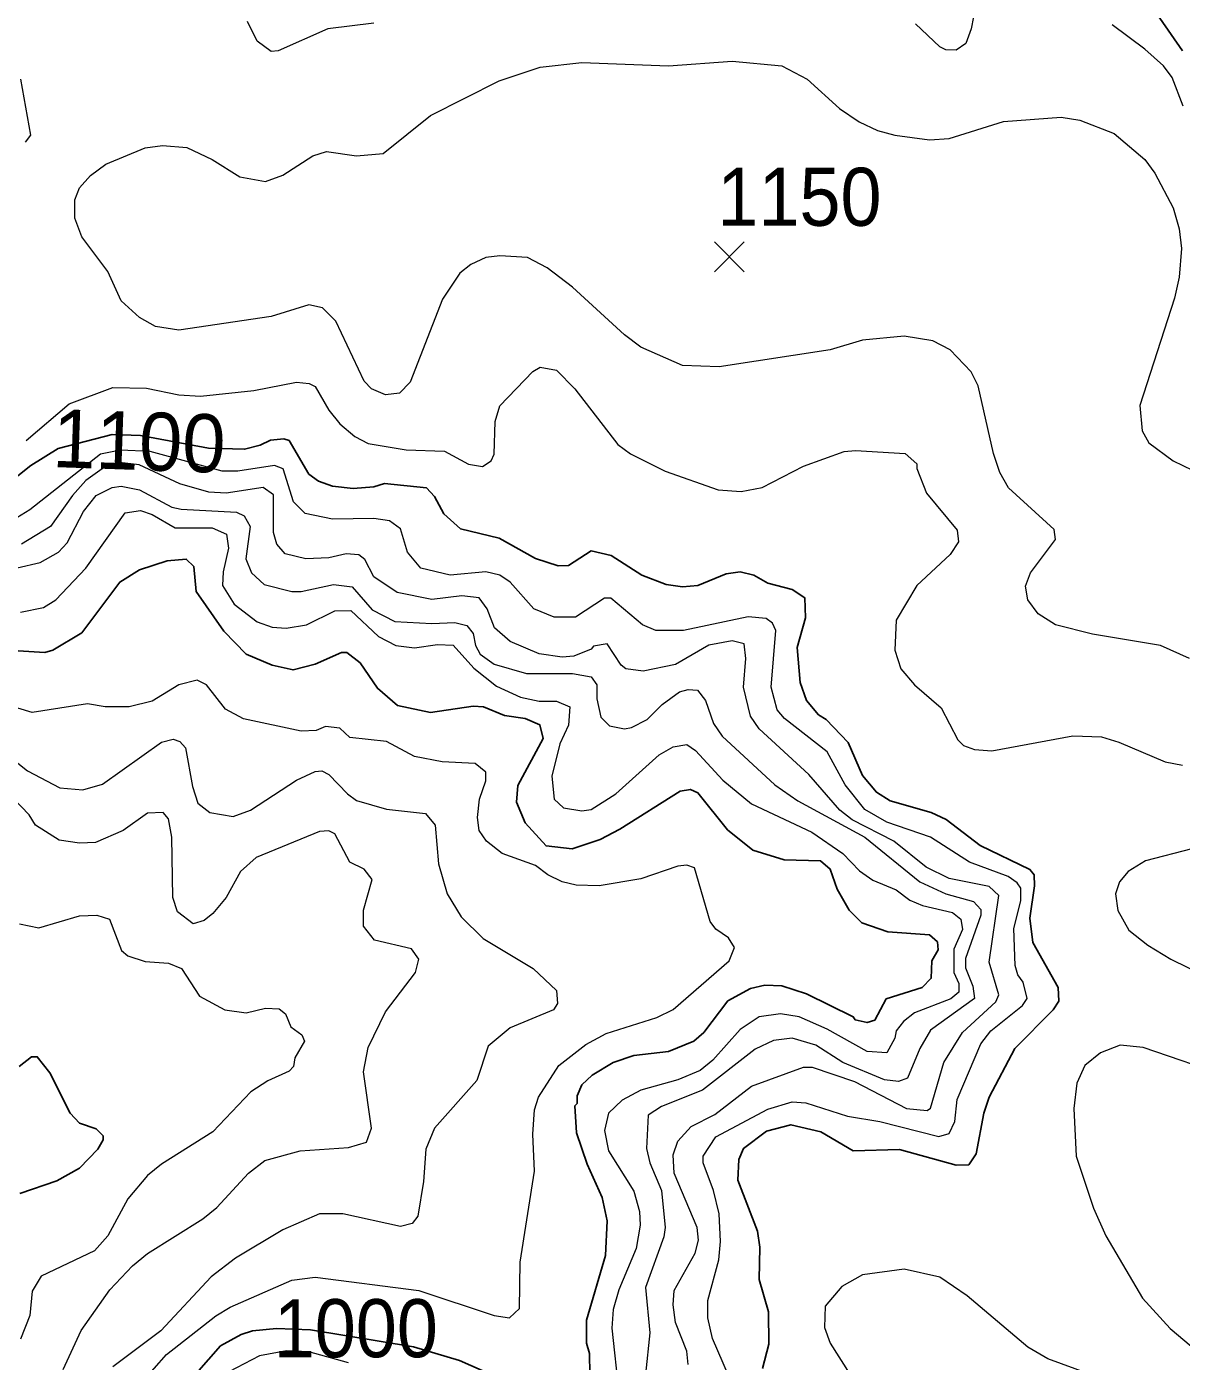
# Model space of a CAD drawing. Extents: x 265 to 291.4, y 7731.5 to 7759.6.
# Drawn here: x 268.417 to 270.007, y 7737.823 to 7739.662 of the extents above; entities that cross this region are included whole.
import ezdxf
from ezdxf.enums import TextEntityAlignment as Align

# ---------------------------------------------------------------- set-up
doc = ezdxf.new("R2010")
doc.units = 0
doc.header["$LTSCALE"] = 0.032
for name, color, linetype, lineweight in [('1', 7, 'Continuous', 25), ('2', 7, 'Continuous', 13), ('21', 7, 'Continuous', 25), ('61', 7, 'Continuous', 13)]:
    doc.layers.add(name, color=color, linetype=linetype, lineweight=lineweight)

msp = doc.modelspace()

# ---------------------------------------------------------------- linework, layer by layer
at = {"layer": '1'}
for points in [[(269.8961, 7739.759), (269.9207, 7739.7312), (269.9391, 7739.7185), (269.9621, 7739.6962), (270.009, 7739.6286)], [(269.1181, 7738.9293), (269.068, 7738.9572), (269.0147, 7738.9699), (268.9916, 7738.9906), (268.9789, 7739.0145), (268.9678, 7739.0264), (268.9097, 7739.0327), (268.8954, 7739.028), (268.8667, 7739.0256), (268.8381, 7739.0288), (268.819, 7739.0359), (268.8055, 7739.0455), (268.7784, 7739.0916), (268.7713, 7739.094), (268.753, 7739.0924), (268.7387, 7739.0852), (268.7172, 7739.0797), (268.6676, 7739.0813), (268.5739, 7739.0986), (268.5348, 7739.0999), (268.4604, 7739.0806), (268.4229, 7739.0574), (268.3497, 7738.9993)], [(269.2979, 7738.8935), (269.2645, 7738.9063), (269.2223, 7738.9333), (269.1945, 7738.9397), (269.1635, 7738.9198), (269.1491, 7738.919), (269.1181, 7738.9293)], [(268.4054, 7738.8021), (268.4419, 7738.7997), (268.4531, 7738.8028), (268.4929, 7738.8267), (268.5453, 7738.8967), (268.5724, 7738.9134), (268.6106, 7738.9262), (268.6368, 7738.9285), (268.6472, 7738.9182), (268.6504, 7738.884), (268.6885, 7738.8291), (268.7196, 7738.7973), (268.7554, 7738.7822), (268.784, 7738.7758), (268.8142, 7738.7838), (268.8508, 7738.7997), (268.858, 7738.7997), (268.8763, 7738.7853), (268.9001, 7738.7504), (268.928, 7738.7265), (268.9733, 7738.7169), (269.0322, 7738.7257), (269.0465, 7738.7249), (269.0752, 7738.713), (269.1038, 7738.709), (269.1237, 7738.7002), (269.1284, 7738.6812), (269.0934, 7738.6167), (269.0918, 7738.5936), (269.1038, 7738.565), (269.1324, 7738.5332), (269.1682, 7738.5292), (269.2072, 7738.5419), (269.2343, 7738.5562), (269.317, 7738.6087), (269.3313, 7738.6111), (269.3416, 7738.6064), (269.3822, 7738.5555), (269.4172, 7738.5276), (269.4602, 7738.5141), (269.5103, 7738.5125), (269.5238, 7738.5014), (269.5333, 7738.4735), (269.55, 7738.4449), (269.5675, 7738.4274), (269.6034, 7738.4147), (269.6606, 7738.4107), (269.6718, 7738.4011), (269.6726, 7738.39), (269.6638, 7738.3749), (269.663, 7738.351), (269.6503, 7738.3383), (269.601, 7738.3224), (269.5851, 7738.293), (269.5747, 7738.2898), (269.558, 7738.2937), (269.5556, 7738.2977), (269.4912, 7738.3295), (269.457, 7738.3407), (269.4339, 7738.3415)], [(269.4307, 7737.8133), (269.4395, 7737.8467), (269.4387, 7737.8912), (269.426, 7737.9358), (269.4268, 7737.9803), (269.4236, 7738.0026), (269.3965, 7738.0726), (269.3981, 7738.1013), (269.4045, 7738.1164), (269.4363, 7738.1402), (269.4697, 7738.149), (269.5111, 7738.1394), (269.5556, 7738.1132), (269.6193, 7738.1148), (269.6972, 7738.0933), (269.7147, 7738.0941), (269.7251, 7738.1092), (269.7354, 7738.1649), (269.7426, 7738.1872), (269.7783, 7738.254), (269.8309, 7738.3073), (269.8388, 7738.3192), (269.838, 7738.3383), (269.803, 7738.4004), (269.799, 7738.4338), (269.8054, 7738.4783), (269.8046, 7738.4934), (269.799, 7738.5006), (269.7306, 7738.534), (269.6837, 7738.5698), (269.663, 7738.5793), (269.6065, 7738.5952), (269.5874, 7738.6072), (269.5683, 7738.6302), (269.5484, 7738.6756), (269.5182, 7738.7074), (269.5079, 7738.7138), (269.4912, 7738.7337), (269.4824, 7738.7583), (269.4785, 7738.8068), (269.4896, 7738.8474), (269.4888, 7738.8752), (269.4713, 7738.8864), (269.4379, 7738.8951), (269.4188, 7738.9063), (269.3997, 7738.911), (269.3806, 7738.9079), (269.3416, 7738.8919), (269.3202, 7738.8904), (269.2979, 7738.8935)], [(269.4339, 7738.3415), (269.414, 7738.3367), (269.383, 7738.32), (269.3496, 7738.2763), (269.3361, 7738.2643), (269.3011, 7738.25), (269.2534, 7738.2444)], [(268.4077, 7738.0543), (268.4587, 7738.0718), (268.4897, 7738.0893), (268.5151, 7738.1156), (268.5223, 7738.1283), (268.5223, 7738.1339), (268.5128, 7738.1434), (268.4897, 7738.1514), (268.4769, 7738.1649), (268.4491, 7738.2206), (268.4316, 7738.2428), (268.4237, 7738.2428), (268.4069, 7738.2293)], [(269.2534, 7738.2444), (269.2247, 7738.2349), (269.1961, 7738.2174), (269.1817, 7738.2039), (269.1754, 7738.1888), (269.1754, 7738.1784), (269.1722, 7738.1752), (269.1746, 7738.1378), (269.1889, 7738.0949), (269.2096, 7738.0488), (269.2167, 7738.0169), (269.2144, 7737.9692), (269.1881, 7737.8801), (269.1881, 7737.8483), (269.1921, 7737.834), (269.1929, 7737.8053)], [(269.0799, 7737.795), (269.0131, 7737.8244), (268.9499, 7737.8433), (268.8078, 7737.8666), (268.7613, 7737.8685), (268.7283, 7737.865), (268.7124, 7737.8602), (268.6838, 7737.8443), (268.6376, 7737.7918)]]:
    msp.add_lwpolyline(points, dxfattribs=at)
at = {"layer": '2'}
for points in [[(269.7243, 7739.6922), (269.7179, 7739.6588), (269.7107, 7739.6389), (269.6972, 7739.6294), (269.6829, 7739.6302), (269.675, 7739.6341), (269.6415, 7739.666)], [(268.8954, 7739.6668), (268.8317, 7739.6588), (268.7633, 7739.6286), (268.7538, 7739.6278), (268.7347, 7739.6421), (268.7212, 7739.6692)], [(270.0098, 7739.5522), (269.9947, 7739.592), (269.9828, 7739.6079), (269.9574, 7739.631), (269.912, 7739.6644)], [(268.8302, 7739.4902), (268.8715, 7739.4838), (268.9081, 7739.487), (268.9733, 7739.5395), (269.068, 7739.5872), (269.1245, 7739.6063), (269.1818, 7739.6127)], [(269.1818, 7739.6127), (269.3011, 7739.6079), (269.3886, 7739.6143), (269.457, 7739.6079), (269.492, 7739.5896), (269.5365, 7739.549), (269.5636, 7739.5307), (269.589, 7739.5188), (269.6129, 7739.5124), (269.6606, 7739.5061), (269.6877, 7739.5077), (269.7625, 7739.5315), (269.842, 7739.5371), (269.8675, 7739.5331), (269.9152, 7739.5148), (269.9573, 7739.479), (269.9709, 7739.4599), (269.9963, 7739.4122), (270.0043, 7739.3836), (270.0075, 7739.3565), (270.0043, 7739.3168), (269.9979, 7739.2881), (269.9502, 7739.1402), (269.9534, 7739.1052), (269.9629, 7739.0884), (269.9963, 7739.0638), (270.0361, 7739.0447)], [(268.4085, 7739.5896), (268.4221, 7739.5124), (268.4149, 7739.5029)], [(270.0186, 7738.7917), (269.9788, 7738.8092), (269.885, 7738.8251), (269.8341, 7738.8379), (269.8102, 7738.853), (269.7959, 7738.8721), (269.7927, 7738.8912), (269.7998, 7738.9095), (269.834, 7738.9556), (269.8324, 7738.9691), (269.7696, 7739.0264), (269.7577, 7739.0479), (269.7489, 7739.0741), (269.7275, 7739.1672), (269.7179, 7739.1863), (269.6893, 7739.2165), (269.6654, 7739.2292), (269.6256, 7739.2356), (269.5684, 7739.23), (269.5238, 7739.2165), (269.3711, 7739.1935), (269.3202, 7739.195), (269.2629, 7739.2205), (269.2406, 7739.2372), (269.169, 7739.3032), (269.134, 7739.3295), (269.107, 7739.3438), (269.0688, 7739.3462), (269.0497, 7739.3438), (269.029, 7739.3342), (269.0139, 7739.3223), (268.99, 7739.2865), (268.9455, 7739.172), (268.9304, 7739.1569), (268.9113, 7739.1545), (268.8922, 7739.1632), (268.8818, 7739.1736), (268.8429, 7739.2563), (268.8246, 7739.2746), (268.8055, 7739.2786), (268.7538, 7739.2627), (268.6265, 7739.2436), (268.5947, 7739.2491), (268.5724, 7739.2611), (268.547, 7739.2841), (268.5287, 7739.3247), (268.4929, 7739.3724), (268.4833, 7739.3979), (268.4833, 7739.4234), (268.4897, 7739.44), (268.5048, 7739.4568), (268.5263, 7739.4727), (268.5804, 7739.4949), (268.6042, 7739.4981), (268.6376, 7739.4957), (268.6727, 7739.479), (268.7108, 7739.4552), (268.7458, 7739.4488), (268.7697, 7739.4575), (268.8111, 7739.4838), (268.8302, 7739.4902)], [(268.4165, 7739.0916), (268.4754, 7739.1425), (268.5358, 7739.1648), (268.582, 7739.164), (268.6265, 7739.1545), (268.6567, 7739.1529), (268.7299, 7739.1608), (268.7888, 7739.172), (268.8063, 7739.1704), (268.8142, 7739.1664), (268.8333, 7739.1338), (268.8484, 7739.1147), (268.8691, 7739.0972), (268.8874, 7739.0876), (268.9399, 7739.0789), (268.9924, 7739.0773), (269.0258, 7739.059), (269.0449, 7739.0558), (269.057, 7739.0637), (269.061, 7739.073), (269.0624, 7739.1179), (269.0688, 7739.1394), (269.1141, 7739.1871), (269.1245, 7739.1927), (269.1467, 7739.1887), (269.1722, 7739.1632), (269.2311, 7739.0861), (269.2486, 7739.0733), (269.2963, 7739.0495), (269.3695, 7739.024), (269.4013, 7739.0216), (269.43, 7739.0272), (269.4872, 7739.0566), (269.5429, 7739.0765), (269.5588, 7739.0781), (269.6272, 7739.0741), (269.6431, 7739.0598), (269.6431, 7739.0534), (269.6567, 7739.0192), (269.6988, 7738.9683), (269.7004, 7738.9524)], [(269.6956, 7738.1538), (269.6988, 7738.184), (269.7314, 7738.2604), (269.745, 7738.2786), (269.7887, 7738.3136), (269.7951, 7738.3232), (269.7895, 7738.3455), (269.7823, 7738.3558), (269.7784, 7738.3685), (269.7768, 7738.4195), (269.7863, 7738.4576), (269.7863, 7738.4751), (269.7815, 7738.4823), (269.7688, 7738.491), (269.7155, 7738.5109), (269.6622, 7738.5451), (269.6018, 7738.5658), (269.5715, 7738.5833), (269.5445, 7738.6175), (269.5198, 7738.6629), (269.461, 7738.709), (269.4506, 7738.7209), (269.4427, 7738.752), (269.449, 7738.8299), (269.4443, 7738.8403), (269.4355, 7738.8466), (269.4109, 7738.849), (269.3218, 7738.8299), (269.2836, 7738.8299), (269.2653, 7738.8379), (269.2215, 7738.8745), (269.2128, 7738.8745), (269.173, 7738.8482), (269.1436, 7738.8482), (269.1157, 7738.8601), (269.0831, 7738.8967), (269.0688, 7738.9063), (269.0497, 7738.911), (269.0004, 7738.9063), (268.9598, 7738.9158), (268.9415, 7738.9381), (268.932, 7738.9699), (268.9169, 7738.9811), (268.8954, 7738.9842), (268.8381, 7738.9834), (268.8007, 7738.9914), (268.7848, 7739.0073), (268.7705, 7739.0527), (268.7586, 7739.0574), (268.7077, 7739.0495), (268.6862, 7739.0495), (268.587, 7739.0767), (268.5464, 7739.0787), (268.5186, 7739.0728), (268.4213, 7738.9962), (268.3974, 7738.9818)], [(269.3281, 7737.8189), (269.3265, 7737.8372), (269.3106, 7737.8769), (269.3074, 7737.9008), (269.309, 7737.9207), (269.3377, 7737.9724), (269.3424, 7737.9899), (269.3408, 7738.0074), (269.309, 7738.0822), (269.3074, 7738.1076), (269.3138, 7738.1267), (269.3321, 7738.1466), (269.3647, 7738.1633), (269.4156, 7738.2023), (269.4872, 7738.2285), (269.4991, 7738.2285), (269.5572, 7738.2086), (269.6288, 7738.1713), (269.6575, 7738.1689), (269.6622, 7738.172), (269.6805, 7738.2349), (269.706, 7738.2763), (269.7521, 7738.3184), (269.7561, 7738.3279), (269.7426, 7738.3733), (269.7561, 7738.4648), (269.7426, 7738.4775), (269.6877, 7738.4886), (269.6559, 7738.5038), (269.6113, 7738.5396), (269.554, 7738.569), (269.5373, 7738.5825), (269.4944, 7738.6318), (269.426, 7738.6947), (269.414, 7738.7122), (269.4045, 7738.752), (269.4077, 7738.7917), (269.4053, 7738.8116), (269.3886, 7738.8156), (269.3568, 7738.81), (269.3106, 7738.783), (269.2661, 7738.7742), (269.2422, 7738.7774), (269.2358, 7738.7822), (269.2168, 7738.8116), (269.1977, 7738.8084), (269.1945, 7738.8044), (269.1706, 7738.7949), (269.1547, 7738.7933), (269.1229, 7738.7981), (269.0831, 7738.8148), (269.0616, 7738.8339), (269.0513, 7738.8601), (269.0402, 7738.8752), (269.0163, 7738.8776), (268.9749, 7738.8729), (268.9272, 7738.8824), (268.8954, 7738.9039), (268.8827, 7738.9278), (268.8747, 7738.9341), (268.8572, 7738.9357), (268.8333, 7738.9301), (268.8015, 7738.9286), (268.7729, 7738.9357), (268.7617, 7738.9492), (268.757, 7738.9652), (268.757, 7739.0169), (268.7427, 7739.0272), (268.6917, 7739.0192), (268.6679, 7739.0208), (268.6281, 7739.032), (268.5719, 7739.0584), (268.5447, 7739.0617), (268.5242, 7739.055), (268.4984, 7739.0367), (268.4801, 7739.0161), (268.4499, 7738.9731), (268.4101, 7738.9492)], [(268.3401, 7738.9015), (268.4356, 7738.9238), (268.4611, 7738.9381), (268.473, 7738.9508), (268.4952, 7738.9938), (268.5127, 7739.0161), (268.535, 7739.0272), (268.547, 7739.0288), (268.5724, 7739.024), (268.617, 7739.0001), (268.6297, 7738.997), (268.7061, 7738.993), (268.7164, 7738.9882), (268.7251, 7738.9731), (268.7188, 7738.9286), (268.7267, 7738.9095), (268.7442, 7738.8936), (268.7824, 7738.884), (268.7952, 7738.884), (268.8397, 7738.8936), (268.8652, 7738.8904), (268.893, 7738.8586), (268.924, 7738.8426), (268.9749, 7738.8395), (269.0068, 7738.841), (269.0235, 7738.8371), (269.0322, 7738.8259), (269.0354, 7738.8092), (269.0417, 7738.7973), (269.0608, 7738.7838), (269.1054, 7738.771), (269.169, 7738.771), (269.1945, 7738.7663), (269.2024, 7738.7551), (269.2024, 7738.7361), (269.208, 7738.7106), (269.2199, 7738.6987), (269.2406, 7738.6947), (269.2502, 7738.6963), (269.2716, 7738.7074), (269.2923, 7738.7281), (269.3162, 7738.7456), (269.3281, 7738.7488), (269.3409, 7738.748), (269.352, 7738.7337), (269.3631, 7738.7018), (269.375, 7738.6843), (269.4475, 7738.6175), (269.4793, 7738.5952), (269.5715, 7738.5451), (269.6471, 7738.4839), (269.6829, 7738.4672), (269.7211, 7738.4568), (269.7314, 7738.4457), (269.7314, 7738.4377), (269.71, 7738.3781), (269.71, 7738.3654), (269.7203, 7738.3399), (269.7227, 7738.3232), (269.6622, 7738.2794), (269.6471, 7738.254), (269.6304, 7738.2134), (269.6177, 7738.2086), (269.5986, 7738.211), (269.5413, 7738.2349), (269.5039, 7738.2588), (269.4713, 7738.2683), (269.4459, 7738.2651), (269.4204, 7738.2532), (269.348, 7738.1967), (269.2915, 7738.1744), (269.2732, 7738.1625), (269.2708, 7738.1164), (269.2756, 7738.0965), (269.2915, 7738.0583), (269.2963, 7738.0074), (269.2947, 7737.9947), (269.2693, 7737.9247), (269.2756, 7737.8626), (269.2693, 7737.8053)], [(268.4085, 7738.8554), (268.4404, 7738.8617), (268.4571, 7738.8721), (268.4984, 7738.9158), (268.5525, 7738.9922), (268.574, 7738.9954), (268.5899, 7738.9898), (268.6217, 7738.9715), (268.6727, 7738.9715), (268.6925, 7738.9628), (268.6949, 7738.9437), (268.6878, 7738.9111), (268.687, 7738.892), (268.7029, 7738.8665), (268.7347, 7738.8418), (268.7554, 7738.8347), (268.7745, 7738.8331), (268.8023, 7738.8379), (268.8413, 7738.857), (268.8636, 7738.8578), (268.9017, 7738.822), (268.9256, 7738.8092), (268.9511, 7738.806), (268.9829, 7738.8108), (269.0044, 7738.81), (269.033, 7738.7782), (269.064, 7738.7535), (269.0974, 7738.7384), (269.1229, 7738.7329), (269.1468, 7738.7329), (269.1651, 7738.7249), (269.1635, 7738.6995), (269.1515, 7738.674), (269.1404, 7738.6295), (269.1436, 7738.5976), (269.1563, 7738.5857), (269.1818, 7738.5817), (269.1945, 7738.5833), (269.2287, 7738.6048), (269.2884, 7738.6589), (269.3074, 7738.67), (269.3265, 7738.6732), (269.3385, 7738.6645), (269.3758, 7738.6239), (269.4156, 7738.5913), (269.4984, 7738.5523), (269.5413, 7738.5229), (269.5644, 7738.499), (269.5827, 7738.4863), (269.6145, 7738.4727), (269.6336, 7738.4584), (269.6511, 7738.4513), (269.6925, 7738.4417), (269.7036, 7738.4322), (269.706, 7738.4179), (269.694, 7738.3908), (269.694, 7738.359), (269.7012, 7738.3439), (269.7012, 7738.3319), (269.6901, 7738.3224), (269.64, 7738.3033), (269.6248, 7738.2914), (269.6145, 7738.2786), (269.6129, 7738.2683), (269.6018, 7738.2484), (269.5747, 7738.25), (269.5198, 7738.281), (269.4809, 7738.2977), (269.4554, 7738.3017)], [(269.7004, 7738.9524), (269.6893, 7738.9349), (269.6431, 7738.892), (269.6145, 7738.8442), (269.6129, 7738.8029), (269.6209, 7738.7774), (269.6399, 7738.7551)], [(268.7156, 7738.7082), (268.6909, 7738.7217), (268.6647, 7738.7551), (268.652, 7738.7615), (268.6265, 7738.7551), (268.5899, 7738.7329), (268.5581, 7738.7249), (268.5251, 7738.7249), (268.5008, 7738.7289), (268.4245, 7738.7169), (268.3799, 7738.7305)], [(269.6399, 7738.7551), (269.6766, 7738.7233), (269.6996, 7738.6796), (269.7076, 7738.6716), (269.7227, 7738.666), (269.7466, 7738.6644), (269.8579, 7738.6851), (269.8977, 7738.6835), (269.9216, 7738.6764), (269.9852, 7738.6493), (270.0091, 7738.6446)], [(268.9129, 7738.6772), (268.862, 7738.6827), (268.8484, 7738.6955), (268.8286, 7738.6979), (268.8158, 7738.6923), (268.7952, 7738.6915), (268.7156, 7738.7082)], [(268.3863, 7738.6621), (268.4181, 7738.6366), (268.4626, 7738.6135), (268.4945, 7738.6104), (268.5215, 7738.6183), (268.6026, 7738.6764), (268.6186, 7738.6804), (268.6281, 7738.6772), (268.636, 7738.6684), (268.6456, 7738.6151), (268.6528, 7738.5921), (268.6695, 7738.5793), (268.7013, 7738.5738), (268.7252, 7738.5825), (268.7888, 7738.6239), (268.8142, 7738.6358), (268.8238, 7738.6366), (268.8333, 7738.6318), (268.8588, 7738.6048), (268.8715, 7738.596), (268.9129, 7738.5841), (268.9662, 7738.5777), (268.9797, 7738.5618), (268.9845, 7738.5085), (268.9964, 7738.4672), (269.0155, 7738.4354), (269.0457, 7738.4059), (269.1149, 7738.3645), (269.1468, 7738.3343), (269.1483, 7738.316), (269.1428, 7738.3073), (269.0831, 7738.2826), (269.0529, 7738.2572), (269.037, 7738.2102), (268.9789, 7738.1442), (268.967, 7738.1156), (268.9638, 7738.071), (268.9558, 7738.0233), (268.9479, 7738.013), (268.932, 7738.009), (268.8524, 7738.0265), (268.8206, 7738.0265), (268.7697, 7738.0042), (268.7045, 7737.9652), (268.6711, 7737.9398), (268.6018, 7737.865), (268.5358, 7737.8157)], [(268.5756, 7737.7942), (268.6098, 7737.8324), (268.6774, 7737.8857), (268.6973, 7737.8976), (268.7824, 7737.935), (268.8142, 7737.939), (268.9574, 7737.9207), (269.0608, 7737.8865), (269.0823, 7737.8833), (269.0958, 7737.896), (269.0966, 7737.9597), (269.1165, 7738.0853), (269.1141, 7738.1363), (269.1165, 7738.1697), (269.1221, 7738.1872), (269.1499, 7738.2309), (269.1873, 7738.2596), (269.2152, 7738.2747), (269.2852, 7738.2969), (269.3074, 7738.3081), (269.3846, 7738.3749), (269.3918, 7738.3932), (269.3838, 7738.4067), (269.3663, 7738.4186), (269.3583, 7738.429), (269.3369, 7738.503), (269.3265, 7738.5069), (269.3138, 7738.5054), (269.2629, 7738.4879), (269.2056, 7738.4783), (269.1738, 7738.4791), (269.1547, 7738.4839), (269.1348, 7738.4934), (269.1181, 7738.5062), (269.072, 7738.5229), (269.0505, 7738.5396), (269.0402, 7738.5547), (269.0378, 7738.5722), (269.041, 7738.5976), (269.0497, 7738.6231), (269.0497, 7738.635), (269.0346, 7738.6469), (268.9893, 7738.6493), (268.9511, 7738.6565), (268.9129, 7738.6772)], [(268.4674, 7737.8117), (268.4921, 7737.8658), (268.5318, 7737.9215), (268.5629, 7737.9549), (268.5836, 7737.9716), (268.6599, 7738.0193), (268.679, 7738.0352), (268.7228, 7738.0822), (268.745, 7738.0997), (268.7936, 7738.1132), (268.8604, 7738.1179), (268.885, 7738.1251), (268.8922, 7738.1442), (268.8811, 7738.2222), (268.8874, 7738.2556), (268.9113, 7738.3049), (268.9527, 7738.359), (268.9574, 7738.3773), (268.9471, 7738.3916), (268.8962, 7738.4035), (268.8811, 7738.4226), (268.8811, 7738.4449), (268.893, 7738.4871), (268.8818, 7738.5014), (268.862, 7738.5109), (268.8413, 7738.5499), (268.8333, 7738.5539), (268.8206, 7738.5531), (268.7331, 7738.5173), (268.7116, 7738.4982), (268.6917, 7738.4624), (268.6734, 7738.4401), (268.6615, 7738.4306), (268.6464, 7738.4258), (268.6249, 7738.4425), (268.6185, 7738.4624), (268.617, 7738.5451), (268.6122, 7738.5706), (268.605, 7738.5793), (268.5835, 7738.5785), (268.5501, 7738.5547), (268.512, 7738.538), (268.4897, 7738.5372), (268.4618, 7738.5411), (268.4292, 7738.5618), (268.4205, 7738.5761), (268.399, 7738.5984)], [(270.0218, 7738.5292), (269.9582, 7738.5125), (269.9343, 7738.4982), (269.9224, 7738.4839), (269.9168, 7738.4672), (269.92, 7738.4441), (269.9351, 7738.4171), (269.9613, 7738.3964), (269.9932, 7738.3773), (270.0616, 7738.3439)], [(268.407, 7738.4258), (268.434, 7738.4202), (268.4897, 7738.4369), (268.5136, 7738.4377), (268.5311, 7738.4322), (268.5477, 7738.3892), (268.5565, 7738.382), (268.5804, 7738.3741), (268.6122, 7738.3717), (268.6305, 7738.3645), (268.6551, 7738.3264), (268.6902, 7738.3073), (268.7196, 7738.3033), (268.7458, 7738.3097), (268.7649, 7738.3089), (268.7737, 7738.3017), (268.7808, 7738.2842), (268.7959, 7738.2731), (268.7999, 7738.2643), (268.7864, 7738.2413), (268.7848, 7738.2293), (268.7784, 7738.223), (268.749, 7738.2094), (268.7259, 7738.1943), (268.6734, 7738.1394), (268.6026, 7738.0949), (268.5836, 7738.079), (268.5565, 7738.0472), (268.5287, 7737.9963), (268.5104, 7737.9756), (268.4372, 7737.9406), (268.4245, 7737.9199), (268.4213, 7737.8865), (268.4085, 7737.8539)], [(269.4554, 7738.3017), (269.426, 7738.2977), (269.3997, 7738.2802), (269.3623, 7738.2381), (269.3448, 7738.2238), (269.3138, 7738.211), (269.2629, 7738.1967)], [(270.0759, 7738.2142), (269.955, 7738.2556), (269.9232, 7738.2588), (269.8961, 7738.2484), (269.8746, 7738.2309), (269.8635, 7738.2063), (269.8595, 7738.1713), (269.8627, 7738.106), (269.8866, 7738.0344), (269.9033, 7737.9963), (269.9542, 7737.9103), (269.9923, 7737.8682), (270.0703, 7737.8029)], [(269.2629, 7738.1967), (269.2374, 7738.1832), (269.2184, 7738.1649), (269.2128, 7738.141), (269.2183, 7738.1132), (269.2533, 7738.0575), (269.2613, 7738.0297), (269.2621, 7738.0106), (269.2565, 7737.9788), (269.2327, 7737.9215), (269.2247, 7737.8944), (269.2231, 7737.869), (269.2327, 7737.7799)], [(269.3838, 7737.8037), (269.3615, 7737.8547), (269.3552, 7737.8833), (269.3552, 7737.9072), (269.3703, 7737.9628), (269.3727, 7737.9883), (269.3711, 7738.0265), (269.3631, 7738.0583), (269.3488, 7738.0965), (269.3488, 7738.106), (269.3663, 7738.1323), (269.4379, 7738.1705), (269.4713, 7738.1808)], [(269.4713, 7738.1808), (269.4904, 7738.1792), (269.5477, 7738.1609), (269.5922, 7738.1537), (269.6734, 7738.1331), (269.6877, 7738.137), (269.6956, 7738.1538)], [(269.8802, 7737.8061), (269.8237, 7737.8268), (269.7959, 7737.8427), (269.7123, 7737.9135), (269.675, 7737.939), (269.6256, 7737.9501), (269.5684, 7737.9422), (269.5397, 7737.9262), (269.5167, 7737.8992), (269.5159, 7737.8698), (269.5238, 7737.8483), (269.566, 7737.7815)], [(268.8604, 7737.8212), (268.8055, 7737.8362), (268.7749, 7737.8376), (268.7379, 7737.8308), (268.6957, 7737.8085)]]:
    msp.add_lwpolyline(points, dxfattribs=at)
at = {"layer": '21'}
for p, q in [((269.3643, 7739.3654), (269.4055, 7739.3242)), ((269.4055, 7739.3654), (269.3643, 7739.3242))]:
    msp.add_line(p, q, dxfattribs=at)

# ---------------------------------------------------------------- texts
at = {"layer": '61', "width": 0.95}
for s, p in [('1150', (269.4815, 7739.3876)), ('1000', (268.8704, 7737.8288))]:
    msp.add_text(s, height=0.08, dxfattribs=at).set_placement(p, align=Align.CENTER)
at = {"layer": '61'}
msp.add_text('1100', height=0.08, rotation=358.024, dxfattribs=at).set_placement((268.5706, 7739.0512), align=Align.CENTER)

doc.saveas('drawing.dxf')
